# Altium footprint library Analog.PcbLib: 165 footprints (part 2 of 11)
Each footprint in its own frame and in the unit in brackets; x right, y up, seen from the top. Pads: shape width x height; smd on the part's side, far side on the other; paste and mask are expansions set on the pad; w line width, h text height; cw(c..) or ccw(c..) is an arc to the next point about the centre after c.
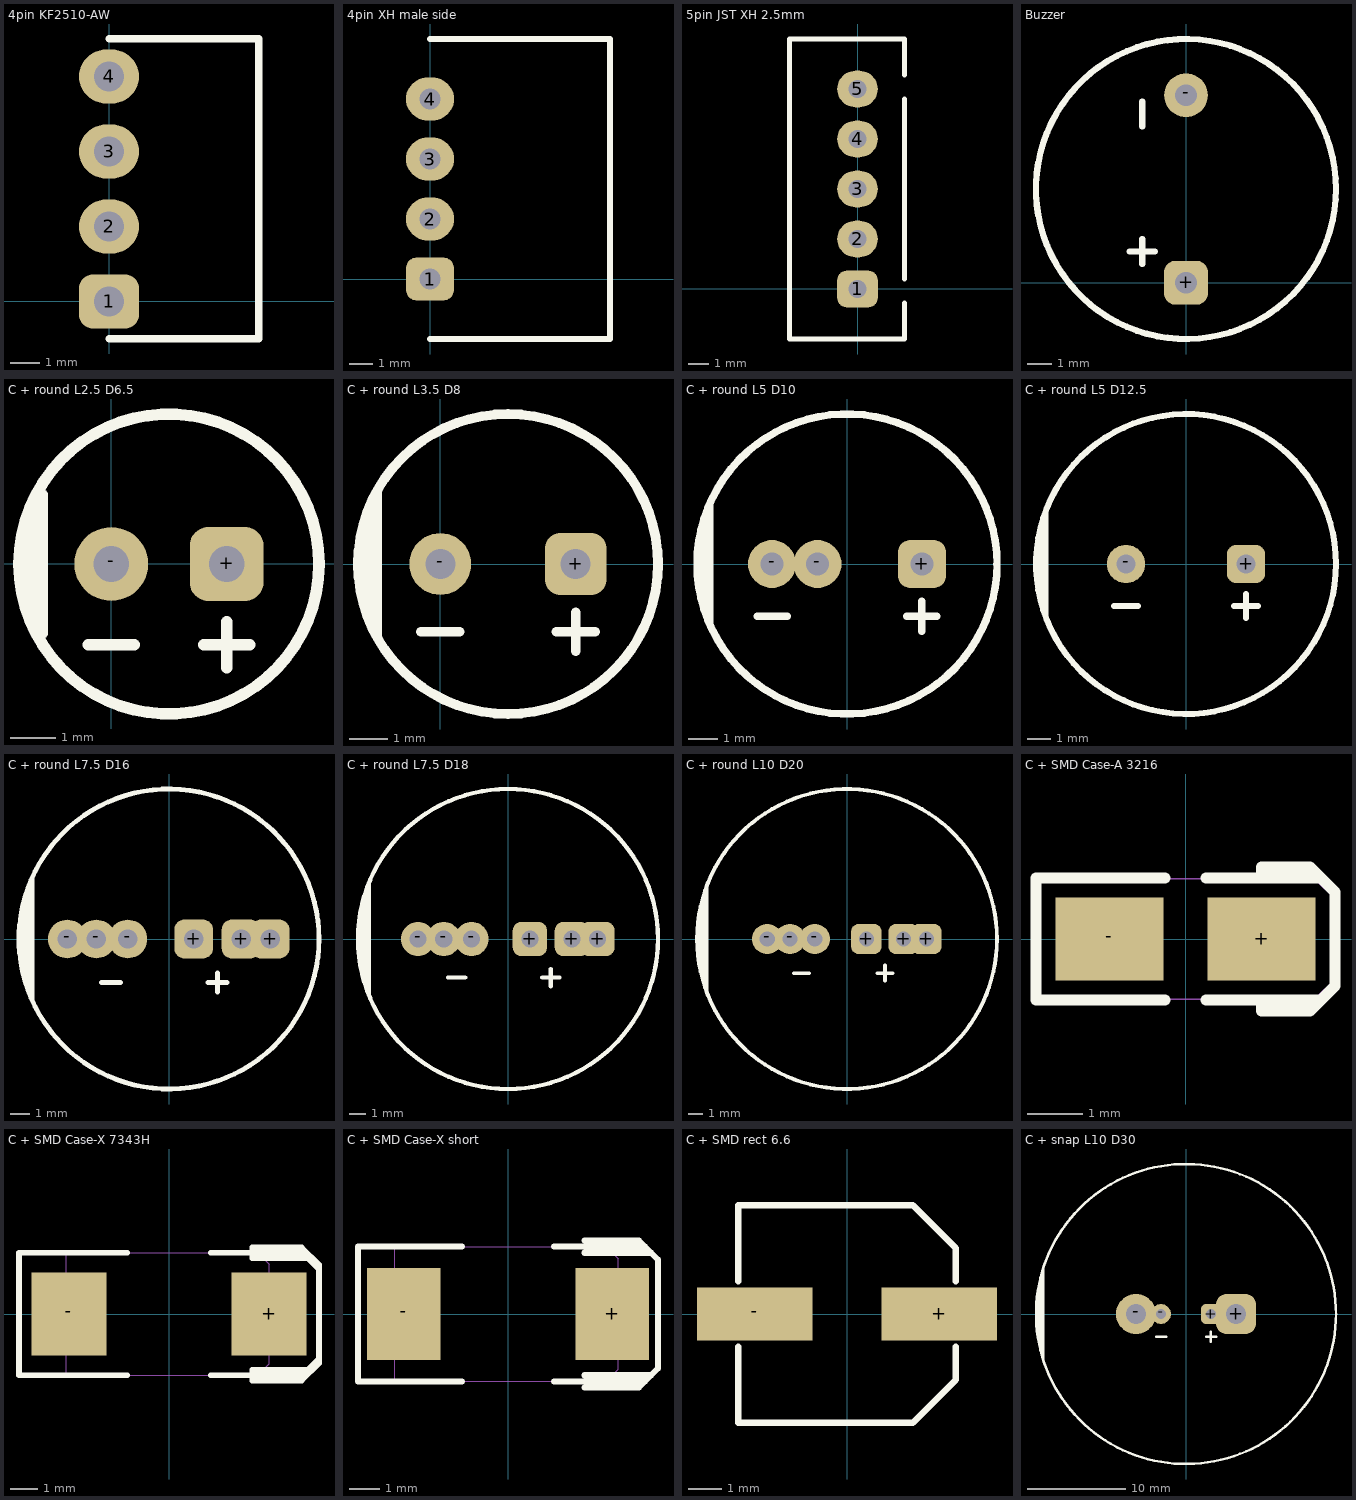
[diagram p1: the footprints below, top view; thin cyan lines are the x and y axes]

## 4pin KF2510-AW [mil] "KF2510-AW"
height 228.35
pads (4):
  rrect50% 80x72 hole 40: 1(0,0)
  oval 80x72 hole 40: 2(0,100) 3(0,200) 4(0,300)
Top Overlay:
  lines w10: 0,-50 200,-50 200,350 0,350

## 4pin XH male side [mil] "S4B-XH-A-1"
height 228.35
pads (4):
  rrect50% 80x72 hole 35.43: 1(0,0)
  oval 80x72 hole 35.43: 2(0,100) 3(0,200) 4(0,300)
Top Overlay:
  lines w10: 0,-100 300,-100 300,400 0,400

## 5pin JST XH 2.5mm [mil] "B4B-XH"
height 275.59
pads (5):
  rrect50% 80x72 hole 35.43: 1(0,0)
  oval 80x72 hole 35.43: 2(0,98.43) 3(0,196.85) 4(0,295.28) 5(0,393.7)
Top Overlay:
  lines w10: 92.52,-27.56 92.52,-98.43 -133.86,-98.43 -133.86,492.13 92.52,492.13 92.52,421.26 ; 92.52,19.68 92.52,374.02

## Buzzer [mil] "PEC02SAAN"
pads (2):
  rrect50% 70x70 hole 35: +(0,0)
  round 70 hole 35: -(0,300)
Top Overlay:
  circle w10: c0,150 r240
  lines w10: -90,50 -50,50 ; -70,30 -70,70 ; -70,250 -70,290
Bottom Overlay:
  lines w10: 50,50 90,50 ; 70,30 70,70 ; 70,250 70,290

## C + round L2.5 D6.5 [mil]
height 472.44
pads (2):
  rrect50% 64x64 hole 31: +(100,0)
  round 64 hole 31: -(0,0)
Top Overlay:
  circle w10: c50,0 r130
  lines w10: -20,-70 20,-70 ; 80,-70 120,-70 ; 100,-90 100,-50 ; -70,-50 -70,50 -60,60 -60,-60 -70,-50
Bottom Overlay:
  lines w10: -20,70 20,70 ; 80,70 120,70 ; 100,50 100,90

## C + round L3.5 D8 [mil]
height 460
pads (2):
  rrect50% 64x64 hole 31: +(140,0)
  round 64 hole 31: -(0,0)
Top Overlay:
  circle w10: c70,0 r155
  lines w10: -75,-50 -75,50 ; -70,-65 -70,65 ; -65,-75 -65,75 ; -20,-70 20,-70 ; 120,-70 160,-70 ; 140,-90 140,-50
Bottom Overlay:
  lines w10: -20,70 20,70 ; 120,70 160,70 ; 140,50 140,90

## C + round L5 D10 [mil]
height 315
pads (3):
  rrect50% 64x64 hole 31: +(100,0)
  round 64 hole 31: -(-100,0) -(-39.37,0)
Top Overlay:
  circle w10: c0,0 r200
  lines w10: -193,-50 -193,50 ; -188,-65 -188,65 ; -183,-80 -183,80 ; -120,-70 -80,-70 ; 80,-70 120,-70 ; 100,-90 100,-50
Bottom Overlay:
  lines w10: -120,70 -80,70 ; 80,70 120,70 ; 100,50 100,90

## C + round L5 D12.5 [mil]
height 315
pads (2):
  rrect50% 64x64 hole 31: +(100,0)
  round 64 hole 31: -(-100,0)
Top Overlay:
  circle w10: c0,0 r250
  lines w10: -244,-50 -244,50 ; -239,-65 -239,65 ; -234,-86 -234,86 ; -120,-70 -80,-70 ; 80,-70 120,-70 ; 100,-90 100,-50
Bottom Overlay:
  lines w10: -120,70 -80,70 ; 80,70 120,70 ; 100,50 100,90

## C + round L7.5 D16 [mil]
height 800
pads (6):
  rrect50% 80x80 hole 40: +(51,0) +(149,0) +(209,0)
  round 80 hole 40: -(-210,0) -(-150,0) -(-85,0)
Top Overlay:
  circle w10: c0,0 r310
  lines w10: -301,-60 -301,60 ; -293,-100 -293,100 ; -283,-125 -283,125 ; -140,-90 -100,-90 ; 80,-90 120,-90 ; 100,-110 100,-70
Bottom Overlay:
  lines w10: -140,90 -100,90 ; 80,90 120,90 ; 100,70 100,110

## C + round L7.5 D18 [mil]
height 800
pads (6):
  rrect50% 80x80 hole 40: +(51,0) +(149,0) +(209,0)
  round 80 hole 40: -(-210,0) -(-150,0) -(-85,0)
Top Overlay:
  circle w10: c0,0 r350
  lines w10: -345,-60 -345,60 ; -335,-100 -335,100 ; -325,-130 -325,130 ; -140,-90 -100,-90 ; 80,-90 120,-90 ; 100,-110 100,-70
Bottom Overlay:
  lines w10: -140,90 -100,90 ; 80,90 120,90 ; 100,70 100,110

## C + round L10 D20 [mil]
height 800
pads (6):
  rrect50% 80x80 hole 40: +(51,0) +(149,0) +(209,0)
  round 80 hole 40: -(-210,0) -(-150,0) -(-85,0)
Top Overlay:
  circle w10: c0,0 r395
  lines w10: -390,-60 -390,60 ; -380,-107 -380,107 ; -370,-138 -370,138 ; -140,-90 -100,-90 ; 80,-90 120,-90 ; 100,-110 100,-70
Bottom Overlay:
  lines w10: -140,90 -100,90 ; 80,90 120,90 ; 100,70 100,110

## C + SMD Case-A 3216 [mm]
height 1.6
pads (2):
  rect 1.95x1.5 smd: +(1.375,0) -(-1.375,0)
Top Overlay:
  lines w0.2: -0.375,-1.1 -2.7,-1.1 -2.7,1.1 -0.375,1.1 ; 0.375,-1.1 2.45,-1.1 ; 0.375,1.1 2.45,1.1 ; 1.375,-1.1 1.375,-1.3 2.25,-1.3 2.45,-1.1 ; 1.375,1.1 1.375,1.3 2.25,1.3 2.45,1.1 ; 2.45,-1.1 2.7,-0.85 ; 2.45,-1.1 2.45,-1.1 ; 2.45,1.1 2.7,0.85 2.7,-0.85 ; 2.7,-0.85 2.7,-0.85
Mechanical 13:
  lines w0.025: -2.692,-1.092 -2.692,1.092 2.337,1.092 2.718,0.711 2.718,-0.711 2.337,-1.092 -2.692,-1.092
  text ".Designator" at -1.778,-0.508 h1.02

## C + SMD Case-X 7343H [mm]
height 1.6
pads (2):
  rect 2.7x3 smd: +(3.6,0) -(-3.6,0)
Top Overlay:
  lines w0.2: -1.5,-2.2 -5.4,-2.2 -5.4,2.2 -1.5,2.2 ; 1.5,-2.2 4.8,-2.2 5.4,-1.6 ; 1.5,2.2 4.8,2.2 5.4,1.6 ; 5,-2 3,-2 3,-2.4 4.775,-2.4 5.4,-1.775 5.4,-1.6 ; 5,2 3,2 3,2.4 4.775,2.4 5.4,1.775 5.4,1.6 ; 5.4,-1.6 5.4,1.6
Mechanical 13:
  lines w0.025: -3.7,-2.2 -3.7,2.2 3.2,2.2 3.6,1.8 3.6,-1.8 3.2,-2.2 -3.7,-2.2
  text ".Designator" at -1.778,-0.508 h1.02

## C + SMD Case-X short [mm]
height 1.6
pads (2):
  rect 2.4x3 smd: +(3.4,0) -(-3.4,0)
Top Overlay:
  lines w0.2: -1.5,-2.2 -4.9,-2.2 -4.9,2.2 -1.5,2.2 ; 1.5,-2.2 4.475,-2.2 ; 1.5,2.2 4.475,2.2 ; 2.5,-2.4 4.275,-2.4 4.9,-1.775 4.9,-1.6 4.9,1.6 4.9,1.775 4.275,2.4 2.5,2.4 ; 2.5,-2 4.675,-2 ; 2.5,2 4.675,2 ; 3,-2.4 3,-2 ; 3,2 3,2.4
Mechanical 13:
  lines w0.025: -3.7,-2.2 3.2,-2.2 3.6,-1.8 3.6,1.8 3.2,2.2 -3.7,2.2 -3.7,-2.2
  text ".Designator" at -1.778,-0.508 h1.02

## C + SMD rect 6.6 [mm]
height 7.7
pads (2):
  rect 3.5x1.6 smd: +(2.8,0) -(-2.8,0)
Top Overlay:
  lines w0.2: -3.3,-1 -3.3,-3.3 2,-3.3 3.3,-2 3.3,-1 ; -3.3,1 -3.3,3.3 2,3.3 3.3,2 3.3,1

## C + snap L10 D30 [mil]
height 2000
pads (4):
  rrect50% 80x80 hole 40: +(100,0)
  rrect50% 160x160 hole 80: +(200,0)
  round 160 hole 80: -(-200,0)
  round 80 hole 40: -(-100,0)
Top Overlay:
  circle w10: c0,0 r600
  lines w10: -591,-100 -591,100 ; -582,-145 -582,145 ; -572,-180 -572,180 ; -120,-90 -80,-90 ; 80,-90 120,-90 ; 99.5,-110 99.5,-70
Bottom Overlay:
  lines w10: -120,90 -80,90 ; 80,90 120,90 ; 100.5,70 100.5,110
